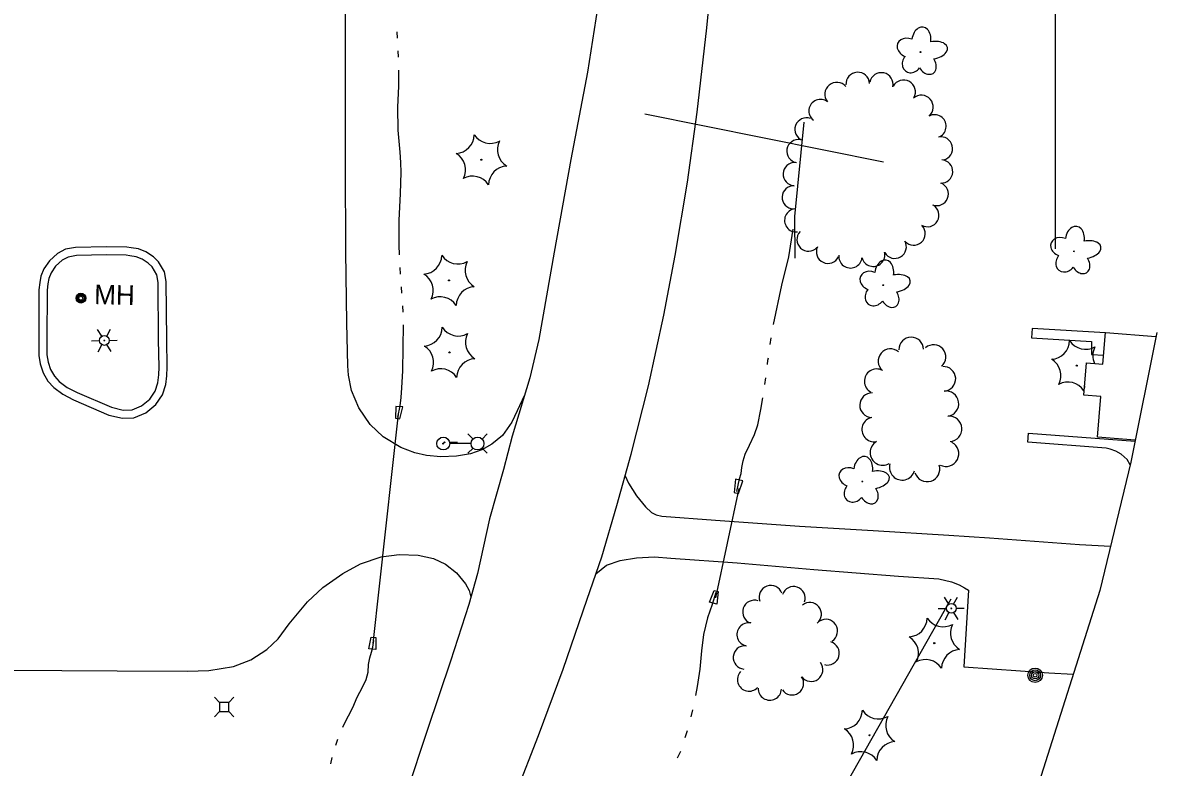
# Model space of a CAD drawing. Extents: x 589250 to 1188077, y 162953 to 363065.
# Drawn here: x 594908 to 595256.8, y 174456.1 to 174685.3 of the extents above; entities that cross this region are included whole.
import ezdxf

# ---------------------------------------------------------------- set-up
doc = ezdxf.new("R2010")
doc.units = 0
for name, color, linetype in [('E_BLD', 7, 'Continuous'), ('E_DRN', 7, 'Continuous'), ('E_DRN_DrainTile', 7, 'Continuous'), ('E_DRN_Pipe', 7, 'Continuous'), ('E_DWY', 7, 'Continuous'), ('E_LAND_TreeLine_P', 7, 'Continuous'), ('E_LAND_Vegetation', 7, 'Continuous'), ('E_LTG', 7, 'Continuous'), ('E_MAP_Limits', 7, 'Continuous'), ('E_MISCPROP', 7, 'Continuous'), ('E_PATH_Sidewalk', 7, 'Continuous'), ('E_RDWY', 7, 'Continuous'), ('E_UTL_AG_Bold', 7, 'Continuous'), ('E_UTL_MH', 7, 'Continuous'), ('E_UTL_MH_Text', 7, 'Continuous'), ('E_WTR_FlowLine', 7, 'Continuous'), ('E_WTR_P', 7, 'Continuous')]:
    doc.layers.add(name, color=color, linetype=linetype)

msp = doc.modelspace()

# ---------------------------------------------------------------- linework, layer by layer
at = {"layer": 'E_BLD'}
for p, q in [((595240.39, 174580.14), (595241.19, 174589.93)), ((595241.19, 174589.93), (595256.69, 174588.66)), ((595234.53, 174570.64), (595235.34, 174580.55)), ((595235.34, 174580.55), (595240.39, 174580.14)), ((595239.74, 174570.21), (595234.53, 174570.64)), ((595238.71, 174557.72), (595239.74, 174570.21)), ((595250.33, 174556.77), (595238.71, 174557.72))]:
    msp.add_line(p, q, dxfattribs=at)
at = {"layer": 'E_DRN'}
for p, q in [((595022.82, 174567.18), (595022.65, 174563.56)), ((595024.96, 174567.02), (595022.82, 174567.18)), ((595024.02, 174563.39), (595024.96, 174567.02)), ((595022.65, 174563.56), (595024.02, 174563.39)), ((595127.33, 174544.75), (595126.87, 174540.66)), ((595129.58, 174544.32), (595127.33, 174544.75)), ((595128.21, 174540.42), (595129.58, 174544.32)), ((595126.87, 174540.66), (595128.21, 174540.42)), ((595119.32, 174506.92), (595120.76, 174510.52)), ((595120.76, 174510.52), (595121.94, 174510.24)), ((595121.94, 174510.24), (595121.57, 174506.28)), ((595121.57, 174506.28), (595119.32, 174506.92)), ((595014.46, 174492.53), (595015.23, 174496.12)), ((595015.23, 174496.12), (595016.6, 174496.05)), ((595016.6, 174496.05), (595016.67, 174492.33)), ((595016.67, 174492.33), (595014.46, 174492.53))]:
    msp.add_line(p, q, dxfattribs=at)
at = {"layer": 'E_DRN_DrainTile'}
for p, q in [((595225.8, 174615.65), (595225.8, 174888.93)), ((595099.41, 174657.27), (595172.9, 174642.48)), ((595085.16, 174316.59), (595193.67, 174507.99))]:
    msp.add_line(p, q, dxfattribs=at)
at = {"layer": 'E_DRN_Pipe'}
for p, q in [((595023.48, 174564.84), (595015.72, 174494.2)), ((595128.33, 174541.95), (595121.13, 174508.28))]:
    msp.add_line(p, q, dxfattribs=at)
at = {"layer": 'E_DWY'}
for p, q in [((595007.26, 174668.49), (595007.34, 174698.72)), ((595007.32, 174641.65), (595007.26, 174668.49)), ((595007.45, 174614.74), (595007.32, 174641.65)), ((594921.12, 174615.55), (594918.68, 174614.29)), ((594924.25, 174616.13), (594921.12, 174615.55)), ((594933.71, 174616.31), (594924.25, 174616.13)), ((594939.98, 174616.18), (594933.71, 174616.31)), ((594941.34, 174616.01), (594939.98, 174616.18)), ((594943.59, 174615.63), (594941.34, 174616.01)), ((594945.9, 174614.74), (594943.59, 174615.63)), ((594948.18, 174613.22), (594945.9, 174614.74)), ((595007.68, 174592.86), (595007.45, 174614.74)), ((594916.17, 174612.03), (594914.45, 174609.48)), ((594918.68, 174614.29), (594916.17, 174612.03)), ((594920.11, 174612.22), (594918.07, 174610.37)), ((594921.94, 174613.16), (594920.11, 174612.22)), ((594924.51, 174613.64), (594921.94, 174613.16)), ((594933.71, 174613.81), (594924.51, 174613.64)), ((594939.8, 174613.69), (594933.71, 174613.81)), ((594940.97, 174613.54), (594939.8, 174613.69)), ((594942.92, 174613.21), (594940.97, 174613.54)), ((594944.74, 174612.5), (594942.92, 174613.21)), ((594946.61, 174611.27), (594944.74, 174612.5)), ((594947.8, 174610.12), (594946.61, 174611.27)), ((594949.79, 174611.67), (594948.18, 174613.22)), ((594951.59, 174608.55), (594949.79, 174611.67)), ((594914.45, 174609.48), (594913.59, 174607.29)), ((594916.67, 174608.31), (594916, 174606.59)), ((594918.07, 174610.37), (594916.67, 174608.31)), ((594949.22, 174607.67), (594947.8, 174610.12)), ((594949.66, 174605.33), (594949.22, 174607.67)), ((594952.16, 174605.58), (594951.59, 174608.55)), ((594913.19, 174605.28), (594912.97, 174603.06)), ((594913.59, 174607.29), (594913.19, 174605.28)), ((594915.66, 174604.91), (594915.47, 174602.93)), ((594916, 174606.59), (594915.66, 174604.91)), ((594949.79, 174587.66), (594949.66, 174605.33)), ((594952.29, 174587.67), (594952.16, 174605.58)), ((594912.96, 174601.67), (594912.92, 174588.91)), ((594912.97, 174603.06), (594912.96, 174601.67)), ((594915.46, 174601.66), (594915.42, 174588.9)), ((594915.47, 174602.93), (594915.46, 174601.66)), ((595008.02, 174579.71), (595007.68, 174592.86)), ((594912.92, 174588.9), (594912.93, 174582.85)), ((594915.42, 174588.9), (594915.43, 174583.05)), ((594949.94, 174579.3), (594949.79, 174587.66)), ((594952.44, 174579.28), (594952.28, 174587.7)), ((594915.43, 174583.05), (594915.77, 174580.84)), ((594912.93, 174582.85), (594913.34, 174580.24)), ((594913.34, 174580.24), (594914.26, 174577.55)), ((594915.77, 174580.84), (594916.55, 174578.58)), ((595008.25, 174576.8), (595008.02, 174579.71)), ((594914.26, 174577.55), (594915.73, 174574.99)), ((594916.55, 174578.58), (594917.76, 174576.46)), ((594917.76, 174576.46), (594919.2, 174574.88)), ((594949.53, 174574.44), (594949.85, 174576.85)), ((594949.85, 174576.85), (594949.94, 174579.3)), ((594951.98, 174573.9), (594952.34, 174576.64)), ((594952.34, 174576.64), (594952.44, 174579.28)), ((595009.17, 174572.1), (595008.25, 174576.8)), ((594915.73, 174574.99), (594917.5, 174573.03)), ((594917.5, 174573.03), (594920.26, 174570.93)), ((594919.2, 174574.88), (594921.61, 174573.05)), ((594921.61, 174573.05), (594924.71, 174571.44)), ((594948.74, 174571.88), (594949.53, 174574.44)), ((594951.01, 174570.78), (594951.98, 174573.9)), ((594920.26, 174570.93), (594923.64, 174569.18)), ((594923.64, 174569.18), (594934.45, 174564.53)), ((594924.71, 174571.44), (594935.24, 174566.91)), ((594944.57, 174567.38), (594947.08, 174569.44)), ((594947.08, 174569.44), (594948.74, 174571.88)), ((594948.94, 174567.73), (594951.01, 174570.78)), ((595011.41, 174566.72), (595009.17, 174572.1)), ((595062.5, 174570.86), (595058.45, 174562.37)), ((594935.24, 174566.91), (594938.9, 174566.04)), ((594938.9, 174566.04), (594941.61, 174566.16)), ((594941.61, 174566.16), (594944.57, 174567.38)), ((594945.87, 174565.22), (594948.94, 174567.73)), ((595014.88, 174561.63), (595011.41, 174566.72)), ((594934.45, 174564.53), (594938.66, 174563.53)), ((594938.66, 174563.53), (594942.16, 174563.68)), ((594942.16, 174563.68), (594945.87, 174565.22)), ((595058.45, 174562.37), (595055.61, 174558.23)), ((595018.87, 174557.82), (595014.88, 174561.63)), ((595024.29, 174554.54), (595018.87, 174557.82)), ((595052.31, 174555.56), (595049.3, 174553.8)), ((595055.61, 174558.23), (595052.31, 174555.56)), ((595028.63, 174552.91), (595024.29, 174554.54)), ((595032.23, 174552.04), (595028.63, 174552.91)), ((595036.65, 174551.69), (595032.23, 174552.04)), ((595041.47, 174551.85), (595036.65, 174551.69)), ((595045.74, 174552.59), (595041.47, 174551.85)), ((595049.3, 174553.8), (595045.74, 174552.59)), ((595093.32, 174545.85), (595094.39, 174543.58)), ((595094.39, 174543.58), (595096.8, 174539.69)), ((595096.8, 174539.69), (595099.59, 174536.25)), ((595099.59, 174536.25), (595101.43, 174534.52)), ((595101.43, 174534.52), (595102.93, 174533.82)), ((595102.93, 174533.82), (595104.66, 174533.37)), ((595104.66, 174533.37), (595121.15, 174532.19)), ((595121.15, 174532.19), (595147.05, 174530.34)), ((595147.05, 174530.34), (595169.69, 174528.99)), ((595169.69, 174528.99), (595193.01, 174527.53)), ((595193.01, 174527.53), (595205.43, 174526.75)), ((595205.43, 174526.75), (595233.22, 174524.73)), ((595233.22, 174524.73), (595242.7, 174524.12)), ((595011.92, 174518.77), (595018.24, 174520.93)), ((595018.24, 174520.93), (595023.85, 174521.6)), ((595023.85, 174521.6), (595029.68, 174521.44)), ((595029.68, 174521.44), (595034.35, 174520.42)), ((595034.35, 174520.42), (595038.1, 174518.68)), ((595091.82, 174519.72), (595096.87, 174520.57)), ((595096.87, 174520.57), (595102.36, 174520.84)), ((595102.36, 174520.84), (595107.39, 174520.49)), ((595107.39, 174520.49), (595127.82, 174519.02)), ((595006.46, 174515.76), (595011.92, 174518.77)), ((595038.1, 174518.68), (595041.5, 174516)), ((595084.36, 174515.69), (595087.59, 174518.28)), ((595087.59, 174518.28), (595091.82, 174519.72)), ((595127.82, 174519.02), (595151.47, 174517.04)), ((595151.47, 174517.04), (595177.46, 174514.95)), ((595000.31, 174511.46), (595006.46, 174515.76)), ((595041.5, 174516), (595044.2, 174512.6)), ((595177.46, 174514.95), (595189.92, 174514.09)), ((595189.92, 174514.09), (595193.79, 174513.24)), ((595193.79, 174513.24), (595196.1, 174512.32)), ((594995.57, 174507.09), (595000.31, 174511.46)), ((595044.2, 174512.6), (595045.31, 174510.55)), ((595045.31, 174510.55), (595045.88, 174508.45)), ((595196.1, 174512.32), (595197.77, 174511.35)), ((595198.98, 174510.61), (595197.57, 174487.05)), ((595197.77, 174511.35), (595198.98, 174510.61)), ((594989.94, 174500.32), (594995.57, 174507.09)), ((594986.55, 174495.61), (594989.94, 174500.32)), ((594978.16, 174489.2), (594983.09, 174492.37)), ((594983.09, 174492.37), (594986.55, 174495.61)), ((594972.88, 174487.16), (594978.16, 174489.2)), ((594903.02, 174486.01), (594937.06, 174485.83)), ((594937.06, 174485.83), (594958.68, 174485.66)), ((594958.68, 174485.66), (594965.2, 174485.88)), ((594965.2, 174485.88), (594972.88, 174487.16)), ((595197.57, 174487.05), (595223.75, 174485.24)), ((595223.75, 174485.24), (595231.24, 174484.73))]:
    msp.add_line(p, q, dxfattribs=at)
at = {"layer": 'E_LAND_TreeLine_P'}
for centre, radius, start, end in [((595158.45, 174663.27), 3.65, 39.7163, 219.7163), ((595164.95, 174666.36), 3.65, 3.7179, 183.7179), ((595172.19, 174666.24), 3.65, 348.4023, 168.4023), ((595179.04, 174663.97), 3.65, 330.9863, 150.9863), ((595153.46, 174658.11), 3.57, 52.2807, 232.2807), ((595184.51, 174659.3), 3.65, 311.2327, 131.2327), ((595188.57, 174653.39), 3.57, 297.6199, 117.6199), ((595149.15, 174652.42), 3.57, 69.6419, 249.6419), ((595146.67, 174645.72), 3.57, 80.2146, 260.2146), ((595190.55, 174646.58), 3.57, 282.3648, 102.3648), ((595190.59, 174639.48), 3.57, 267.1366, 87.1366), ((595145.56, 174638.67), 3.57, 87.3031, 267.3031), ((595189.28, 174632.55), 3.57, 248.3611, 68.3611), ((595145.22, 174631.53), 3.57, 87.3031, 267.3031), ((595186.36, 174626.05), 3.57, 239.8956, 59.8956), ((595145.98, 174624.43), 3.57, 96.4442, 276.4442), ((595182.15, 174620.37), 3.57, 222.1097, 42.1097), ((595149.78, 174618.53), 3.57, 137.0965, 317.0965), ((595176.33, 174616.3), 3.57, 210.0059, 30.0059), ((595155.76, 174614.76), 3.57, 155.0515, 335.0515), ((595169.7, 174613.83), 3.57, 193.6882, 13.6882), ((595162.69, 174613.34), 3.57, 173.0501, 353.0501), ((595181.4, 174584.71), 3.78, 1.0549, 181.0549), ((595175.01, 174581.12), 3.78, 49.5584, 229.5584), ((595188.26, 174582.38), 3.78, 311.0124, 131.0124), ((595170.75, 174574.93), 3.78, 61.8873, 241.8873), ((595191.3, 174575.66), 3.78, 273.3455, 93.3455), ((595169.34, 174567.56), 3.78, 88.6354, 268.6354), ((595192.11, 174568.02), 3.91, 278.6168, 98.6168), ((595169.99, 174560.07), 3.78, 100.5172, 280.5172), ((595193.08, 174560.26), 3.91, 274.0677, 94.0677), ((595172.66, 174552.98), 3.91, 120.3437, 300.3437), ((595192.11, 174552.61), 3.91, 242.7541, 62.7541), ((595178.6, 174548.41), 3.91, 164.2565, 344.2565), ((595186.27, 174547.92), 3.91, 198.0457, 18.0457), ((595138.19, 174508.49), 3.59, 19.8329, 199.8329), ((595145.18, 174508.15), 3.59, 341.308, 161.308), ((595133.12, 174503.94), 3.59, 71.6148, 251.6148), ((595150.17, 174503.26), 3.59, 309.0169, 129.0169), ((595131.34, 174497.01), 3.59, 79.3484, 259.3484), ((595155.12, 174498.04), 3.62, 302.3186, 122.3186), ((595130.2, 174489.93), 3.59, 85.3443, 265.3443), ((595155.65, 174491.21), 3.62, 254.064, 74.064), ((595131.49, 174483.13), 3.59, 137.2737, 317.2737), ((595150.58, 174486.16), 3.62, 216.6889, 36.6889), ((595144.7, 174481.98), 3.59, 214.1255, 34.1255), ((595137.88, 174480.36), 3.59, 177.6212, 357.6212)]:
    msp.add_arc(centre, radius, start, end, dxfattribs=at)
at = {"layer": 'E_LAND_Vegetation'}
for centre, radius in [((595184.22, 174676.23), 0.128), ((595049.11, 174643.09), 0.167), ((595231.48, 174614.9), 0.128), ((595039.15, 174605.96), 0.167), ((595172.79, 174604.5), 0.128), ((595039.29, 174583.81), 0.167), ((595232.34, 174579.73), 0.167), ((595166.35, 174544.06), 0.128), ((595188.5, 174494.32), 0.167), ((595168.57, 174465.97), 0.167)]:
    msp.add_circle(centre, radius, dxfattribs=at)
for centre, radius, start, end in [((595041, 174650.93), 5.9, 273.0879, 358.8528), ((595051.84, 174654.03), 5.9, 213.0879, 298.8528), ((595059.96, 174646.2), 5.91, 153.1276, 238.8037), ((595038.33, 174639.99), 5.9, 333.0832, 58.8481), ((595057.22, 174635.26), 5.9, 93.0879, 178.8528), ((595046.37, 174632.15), 5.9, 33.0879, 118.8528), ((595031.04, 174613.79), 5.9, 273.0879, 358.8528), ((595041.88, 174616.9), 5.9, 213.0879, 298.8528), ((595050, 174609.06), 5.91, 153.1276, 238.8037), ((595028.37, 174602.86), 5.9, 333.0832, 58.8481), ((595047.26, 174598.12), 5.9, 93.0879, 178.8528), ((595036.42, 174595.02), 5.9, 33.0879, 118.8528), ((595031.18, 174591.64), 5.9, 273.0879, 358.8528), ((595042.02, 174594.74), 5.9, 213.0879, 298.8528), ((595050.14, 174586.91), 5.91, 153.1276, 238.8037), ((595224.23, 174587.57), 5.9, 273.0879, 358.8528), ((595235.07, 174590.67), 5.9, 213.0879, 298.8528), ((595028.51, 174580.7), 5.9, 333.0832, 58.8481), ((595243.19, 174582.84), 5.91, 153.1276, 204.9136), ((595047.4, 174575.97), 5.9, 93.0879, 178.8528), ((595221.56, 174576.63), 5.9, 333.0832, 58.8481), ((595036.56, 174572.87), 5.9, 33.0879, 118.8528), ((595229.6, 174568.79), 5.9, 33.0879, 118.8528), ((595240.44, 174571.89), 5.9, 164.4905, 178.8528), ((595180.39, 174502.15), 5.9, 273.0879, 358.8528), ((595191.24, 174505.26), 5.9, 213.0879, 298.8528), ((595199.35, 174497.42), 5.91, 153.1276, 238.8037), ((595177.72, 174491.21), 5.9, 333.0832, 58.8481), ((595196.61, 174486.48), 5.9, 93.0879, 178.8528), ((595185.77, 174483.38), 5.9, 33.0879, 118.8528), ((595160.47, 174473.8), 5.9, 273.0879, 358.8528), ((595171.31, 174476.91), 5.9, 213.0879, 298.8528), ((595179.42, 174469.07), 5.91, 153.1276, 238.8037), ((595157.79, 174462.87), 5.9, 333.0832, 58.8481), ((595165.84, 174455.03), 5.9, 33.0879, 118.8528), ((595176.68, 174458.13), 5.9, 93.0879, 178.8528)]:
    msp.add_arc(centre, radius, start, end, dxfattribs=at)
for centre, major_axis, ratio in [((595180.54, 174677.54), (3.35, -1.35), 0.782863), ((595184.49, 174679.76), (-0.59, -4.18), 0.691916), ((595187.87, 174676.75), (-4.67, -0.86), 0.560249), ((595181.73, 174673.12), (2.15, 2.7), 0.832022), ((595186.17, 174672.73), (-1.95, 3.06), 0.716896), ((595231.74, 174618.42), (-0.59, -4.18), 0.691916), ((595227.79, 174616.21), (3.35, -1.35), 0.782863), ((595235.12, 174615.41), (-4.67, -0.86), 0.560249), ((595173.05, 174608.02), (-0.59, -4.18), 0.691916), ((595228.99, 174611.79), (2.15, 2.7), 0.832022), ((595233.43, 174611.4), (-1.95, 3.06), 0.716896), ((595169.11, 174605.81), (3.35, -1.35), 0.782863), ((595176.43, 174605.01), (-4.67, -0.86), 0.560249), ((595170.3, 174601.39), (2.15, 2.7), 0.832022), ((595174.74, 174601), (-1.95, 3.06), 0.716896), ((595166.61, 174547.58), (-0.59, -4.18), 0.691916), ((595162.67, 174545.36), (3.35, -1.35), 0.782863), ((595169.99, 174544.57), (-4.67, -0.86), 0.560249), ((595163.86, 174540.95), (2.15, 2.7), 0.832022), ((595168.3, 174540.55), (-1.95, 3.06), 0.716896)]:
    msp.add_ellipse(centre, major_axis=major_axis, ratio=ratio, start_param=1.570796, end_param=4.712389, dxfattribs=at)
at = {"layer": 'E_LTG'}
for p, q in [((594932.31, 174588.76), (594931.02, 174590.9)), ((594933.81, 174588.79), (594935.02, 174590.97)), ((594929.09, 174587.4), (594931.59, 174587.45)), ((594934.58, 174587.5), (594937.08, 174587.55)), ((594931.15, 174583.97), (594932.36, 174586.16)), ((594935.15, 174584.05), (594933.86, 174586.19)), ((595039.25, 174556.16), (595041.75, 174556.21)), ((595192.95, 174506.3), (595191.66, 174508.44)), ((595194.45, 174506.33), (595195.66, 174508.52)), ((595189.73, 174504.94), (595192.23, 174504.99)), ((595191.79, 174501.52), (595193, 174503.7)), ((595195.79, 174501.59), (595194.5, 174503.73)), ((595195.23, 174505.04), (595197.73, 174505.09))]:
    msp.add_line(p, q, dxfattribs=at)
for points in [[(595046.55, 174557.14), (595044.93, 174558.75)], [(595049.32, 174557.14), (595050.93, 174558.75)], [(595045.92, 174555.75), (595039.39, 174555.75)], [(595046.55, 174554.37), (595044.93, 174552.75)], [(595049.32, 174554.37), (595050.93, 174552.75)]]:
    msp.add_lwpolyline(points, dxfattribs=at)
for centre, radius in [((594933.09, 174587.47), 1.5), ((594933.09, 174587.47), 0.125), ((595037.38, 174555.75), 1.98), ((595037.38, 174555.75), 0.151), ((595037.75, 174556.13), 0.125), ((595047.93, 174555.75), 1.98), ((595193.73, 174505.02), 1.5), ((595193.73, 174505.02), 0.125)]:
    msp.add_circle(centre, radius, dxfattribs=at)
at = {"layer": 'E_MAP_Limits'}
for p, q in [((595256.95, 174589.94), (595248.98, 174550.03)), ((595248.98, 174550.03), (595239.41, 174510.53)), ((595239.41, 174510.53), (595220.06, 174449.39))]:
    msp.add_line(p, q, dxfattribs=at)
at = {"layer": 'E_MISCPROP'}
for radius in [2.23, 1.67, 1.12, 0.558]:
    msp.add_circle((595219.52, 174484.44), radius, dxfattribs=at)
at = {"layer": 'E_PATH_Sidewalk'}
for p, q in [((595218.61, 174591.15), (595218.45, 174588.32)), ((595241.18, 174589.84), (595218.61, 174591.15)), ((595218.45, 174588.32), (595236.89, 174587.12)), ((595236.89, 174587.12), (595236.83, 174583.18)), ((595236.83, 174583.18), (595240.62, 174582.94)), ((595217.23, 174556.22), (595217.51, 174558.97)), ((595217.51, 174558.97), (595250.27, 174556.46)), ((595241.39, 174554.32), (595217.23, 174556.22)), ((595242.64, 174554.05), (595241.39, 174554.32)), ((595244.36, 174553.44), (595242.64, 174554.05)), ((595246.01, 174552.5), (595244.36, 174553.44)), ((595247.82, 174550.86), (595246.01, 174552.5)), ((595248.79, 174549.24), (595247.82, 174550.86))]:
    msp.add_line(p, q, dxfattribs=at)
at = {"layer": 'E_RDWY'}
for p, q in [((595118.49, 174683.64), (595120.5, 174703.32)), ((595086.03, 174697.53), (595081.72, 174670.04)), ((595115.52, 174657.71), (595118.49, 174683.64)), ((595081.72, 174670.04), (595076.62, 174643.14)), ((595112.53, 174636.24), (595115.52, 174657.71)), ((595076.62, 174643.14), (595071.52, 174614.66)), ((595108.77, 174613.64), (595112.53, 174636.24)), ((595071.52, 174614.66), (595066.83, 174587.77)), ((595105.22, 174595.27), (595108.77, 174613.64)), ((595100.53, 174573.53), (595105.22, 174595.27)), ((595066.83, 174587.77), (595064.04, 174575.94)), ((595064.04, 174575.94), (595058.61, 174558.03)), ((595095.16, 174552.51), (595100.53, 174573.53)), ((595058.61, 174558.03), (595055.94, 174547.72)), ((595090.8, 174536.73), (595095.16, 174552.51)), ((595055.94, 174547.72), (595051.58, 174532.56)), ((595086.14, 174520.88), (595090.8, 174536.73)), ((595051.58, 174532.56), (595047.91, 174515.76)), ((595081.66, 174507.81), (595086.14, 174520.88)), ((595047.91, 174515.76), (595045.27, 174506.27)), ((595045.27, 174506.27), (595039.57, 174488.8)), ((595074.26, 174486.36), (595081.66, 174507.81)), ((595039.57, 174488.8), (595032.56, 174467.79)), ((595066.74, 174465.87), (595074.26, 174486.36)), ((595032.56, 174467.79), (595026.03, 174448.09)), ((595058.78, 174445.68), (595066.74, 174465.87))]:
    msp.add_line(p, q, dxfattribs=at)
at = {"layer": 'E_UTL_AG_Bold'}
for points in [[(594968.56, 174476.1), (594966.97, 174477.69)], [(594971.38, 174476.1), (594972.97, 174477.69)], [(594968.56, 174473.28), (594966.97, 174471.69)], [(594971.38, 174473.28), (594972.97, 174471.69)]]:
    msp.add_lwpolyline(points, dxfattribs=at)
msp.add_lwpolyline([(594968.56, 174473.28), (594971.38, 174473.28), (594971.38, 174476.1), (594968.56, 174476.1)], close=True, dxfattribs=at)
at = {"layer": 'E_UTL_MH'}
for centre, radius in [((594925.87, 174600.5), 1.5), ((594925.87, 174600.5), 1.22), ((594925.86, 174600.49), 0.968), ((594925.84, 174600.48), 0.605)]:
    msp.add_circle(centre, radius, dxfattribs=at)
at = {"layer": 'E_WTR_FlowLine'}
for p, q in [((595023.29, 174680.51), (595023.18, 174682.47)), ((595023.6, 174674.63), (595023.5, 174676.59)), ((595023.74, 174665.75), (595023.74, 174670.7)), ((595023.37, 174659.28), (595023.74, 174665.75)), ((595023.54, 174652.17), (595023.37, 174659.28)), ((595024.11, 174645.43), (595023.54, 174652.17)), ((595024.29, 174642.27), (595024.11, 174645.43)), ((595024.18, 174632.74), (595024.46, 174639.22)), ((595024.46, 174639.22), (595024.29, 174642.27)), ((595023.77, 174624.42), (595024.18, 174632.74)), ((595023.79, 174616.83), (595023.77, 174624.42)), ((595143.76, 174613.24), (595145.11, 174621.74)), ((595023.95, 174613.81), (595023.79, 174616.83)), ((595141.54, 174604.47), (595143.76, 174613.24)), ((595024.26, 174607.93), (595024.16, 174609.89)), ((595024.63, 174602.05), (595024.5, 174604.01)), ((595139.06, 174592.34), (595141.54, 174604.47)), ((595025.03, 174596.17), (595024.9, 174598.13)), ((595025.06, 174585.33), (595025.1, 174592.24)), ((595138.03, 174586.21), (595138.33, 174588.26)), ((595024.91, 174578.1), (595025.06, 174585.33)), ((595137.14, 174580.06), (595137.31, 174581.4)), ((595137.31, 174581.4), (595137.42, 174582.11)), ((595024.64, 174572.87), (595024.91, 174578.1)), ((595024.42, 174569.89), (595024.64, 174572.87)), ((595136.37, 174573.9), (595136.62, 174575.95)), ((595024.14, 174567.4), (595024.42, 174569.89)), ((595135.15, 174566.23), (595135.73, 174569.8)), ((595023.44, 174563.87), (595024.14, 174567.4)), ((595134.16, 174561.56), (595135.15, 174566.23)), ((595133.12, 174558.56), (595134.16, 174561.56)), ((595130.32, 174552.48), (595131.64, 174555.29)), ((595131.64, 174555.29), (595133.12, 174558.56)), ((595129.65, 174550.43), (595130.32, 174552.48)), ((595129.02, 174546.57), (595129.29, 174548.42)), ((595129.29, 174548.42), (595129.65, 174550.43)), ((595127.71, 174541.02), (595128.55, 174544.89)), ((595128.55, 174544.89), (595129.02, 174546.57)), ((595121.31, 174509.88), (595120.15, 174506.22)), ((595120.15, 174506.22), (595118.72, 174502.07)), ((595118.72, 174502.07), (595117.46, 174496.97)), ((595117.46, 174496.97), (595116.81, 174491.94)), ((595015.26, 174491.54), (595015.67, 174493.04)), ((595015.67, 174493.04), (595016.03, 174495.13)), ((595014.4, 174487.75), (595014.77, 174489.81)), ((595014.77, 174489.81), (595015.26, 174491.54)), ((595116.81, 174491.94), (595116.33, 174486.35)), ((595013.68, 174483.12), (595014.28, 174485.38)), ((595014.28, 174485.38), (595014.4, 174487.75)), ((595116.33, 174486.35), (595115.53, 174481.01)), ((595012.52, 174480.73), (595013.68, 174483.12)), ((595010.93, 174477.69), (595012.52, 174480.73)), ((595115.53, 174481.01), (595115.01, 174478.2)), ((595009.59, 174474.49), (595010.93, 174477.69)), ((595006.91, 174469.38), (595009.59, 174474.49)), ((595114.12, 174473.83), (595113.56, 174471.66)), ((595006.5, 174468.45), (595006.91, 174469.38)), ((595004.33, 174462.94), (595004.96, 174464.81)), ((595112.45, 174467.33), (595111.76, 174465.2)), ((595110.36, 174460.96), (595109.35, 174458.96)), ((595002.75, 174457.23), (595003.24, 174459.15))]:
    msp.add_line(p, q, dxfattribs=at)
at = {"layer": 'E_WTR_P'}
msp.add_lwpolyline([(595145.7, 174612.83), (595145.57, 174625.63), (595148.45, 174654.68)], dxfattribs=at)

# ---------------------------------------------------------------- texts
at = {"layer": 'E_UTL_MH_Text'}
msp.add_text('MH', height=6, rotation=358.7294, dxfattribs=at).set_placement((594929.91, 174598.67))

doc.saveas('drawing.dxf')
